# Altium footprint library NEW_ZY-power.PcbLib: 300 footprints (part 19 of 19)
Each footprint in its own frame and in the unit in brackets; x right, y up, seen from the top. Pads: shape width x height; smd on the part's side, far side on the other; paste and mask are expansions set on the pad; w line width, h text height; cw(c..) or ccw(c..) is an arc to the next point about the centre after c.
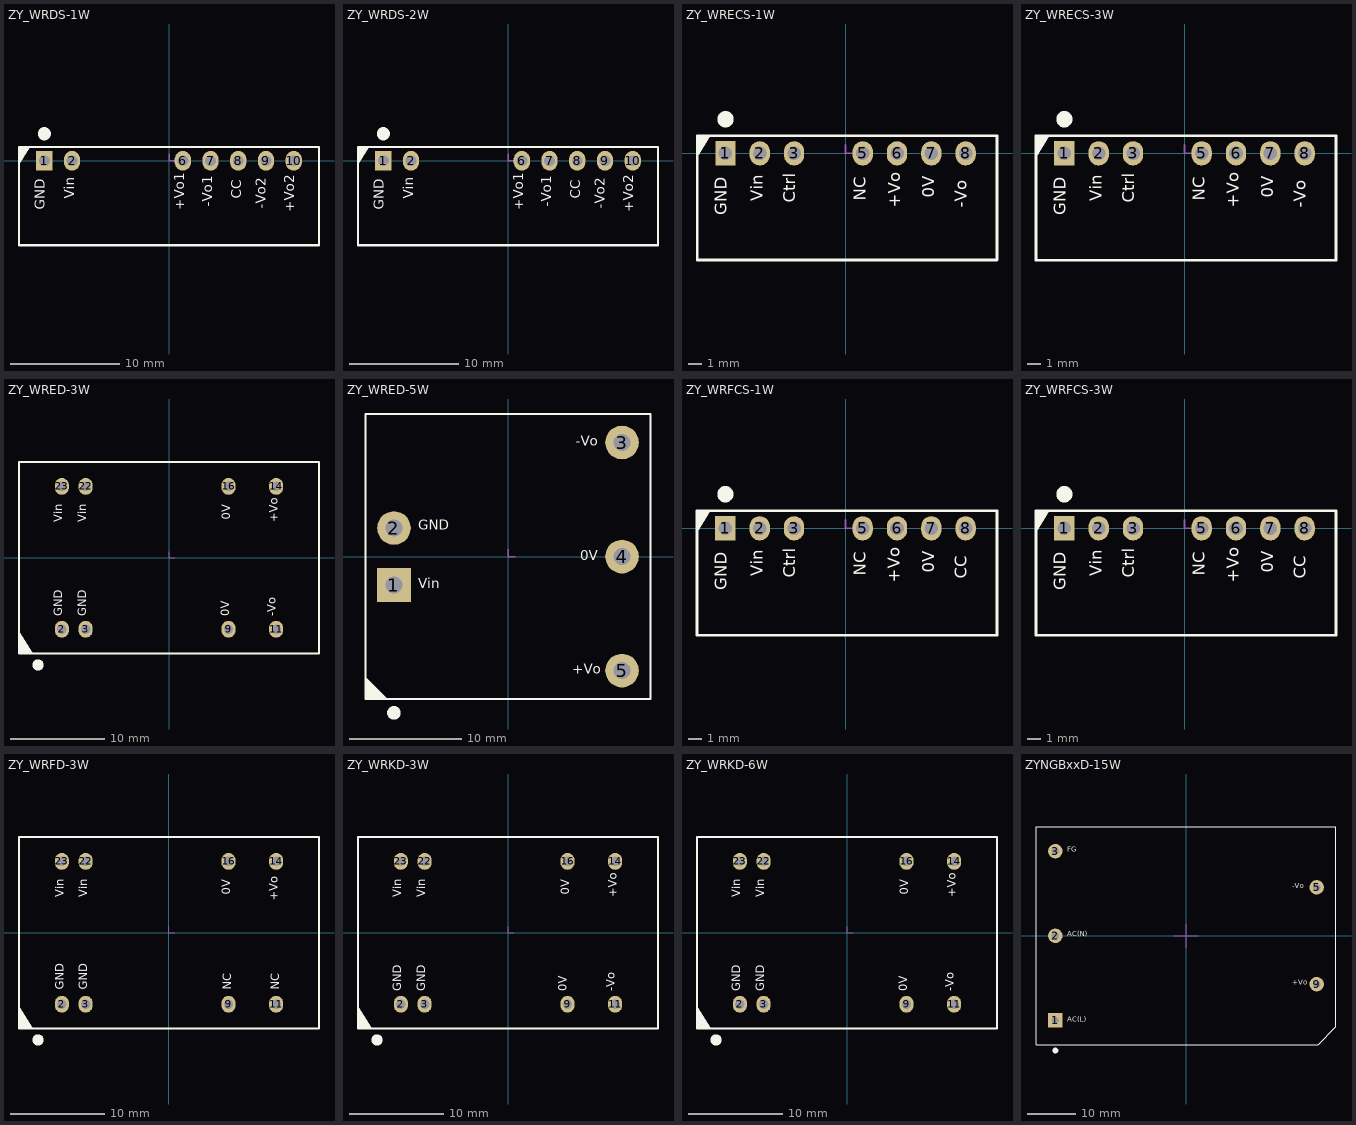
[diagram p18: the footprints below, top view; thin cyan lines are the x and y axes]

## ZY_WRDS-1W [mm]
height 11.5
pads (7):
  rect 1.5x1.8 hole 1: 1(-11.43,0)
  oval 1.5x1.8 hole 1: 2(-8.89,0) 6(1.27,0) 7(3.81,0) 8(6.35,0) 9(8.89,0) 10(11.43,0)
Top Overlay:
  circle w1: c-11.43,2.475 r0.1
  region: -13.75,-0.336 -13.75,1.25 -12.756,1.25
  lines w0.2: -13.75,-7.75 -13.75,1.25 13.75,1.25 13.75,-7.75 -13.75,-7.75
  text "-Vo2" at 9.195,-4.387 h1.52
  text "+Vo2" at 11.811,-4.699 h1.52
  text "CC" at 6.96,-3.469 h1.52
  text "GND" at -11.049,-4.504 h1.52
  text "Vin" at -8.382,-3.494 h1.52
  text "+Vo1" at 1.702,-4.521 h1.52
  text "-Vo1" at 4.267,-4.209 h1.52
Mechanical 15:
  lines w0.127: 0,0.635 0,0 0.635,0

## ZY_WRDS-2W [mm]
height 11.5
pads (7):
  rect 1.5x1.8 hole 1: 1(-11.43,0)
  oval 1.5x1.8 hole 1: 2(-8.89,0) 6(1.27,0) 7(3.81,0) 8(6.35,0) 9(8.89,0) 10(11.43,0)
Top Overlay:
  circle w1: c-11.43,2.475 r0.1
  region: -13.75,-0.336 -13.75,1.25 -12.756,1.25
  lines w0.2: -13.75,-7.75 -13.75,1.25 13.75,1.25 13.75,-7.75 -13.75,-7.75
  text "-Vo2" at 9.195,-4.387 h1.52
  text "+Vo2" at 11.811,-4.699 h1.52
  text "CC" at 6.96,-3.469 h1.52
  text "GND" at -11.049,-4.504 h1.52
  text "Vin" at -8.382,-3.494 h1.52
  text "+Vo1" at 1.702,-4.521 h1.52
  text "-Vo1" at 4.267,-4.209 h1.52
Mechanical 15:
  lines w0.127: 0,0.635 0,0 0.635,0

## ZY_WRECS-1W [mm]
height 12.2
pads (7):
  rect 1.5x1.8 hole 1: 1(-8.89,0)
  oval 1.5x1.8 hole 1: 2(-6.35,0) 3(-3.81,0) 5(1.27,0) 6(3.81,0) 7(6.35,0) 8(8.89,0)
Top Overlay:
  circle w1: c-8.89,2.525 r0.1
  region: -10.998,-0.286 -10.998,1.3 -10.005,1.3
  lines w0.2: -10.99,-7.9 11.21,-7.9 11.21,1.3 -10.99,1.3 -10.99,-7.9
  text "-Vo" at 9.279,-4.03 h1.52
  text "0V" at 6.866,-3.29 h1.52
  text "+Vo" at 4.326,-4.03 h1.52
  text "NC" at 1.786,-3.501 h1.52
  text "Ctrl" at -3.421,-3.646 h1.52
  text "Vin" at -5.834,-3.562 h1.52
  text "GND" at -8.501,-4.572 h1.52
Mechanical 15:
  lines w0.127: 0,0.635 0,0 0.635,0

## ZY_WRECS-3W [mm]
height 12.2
pads (7):
  rect 1.5x1.8 hole 1: 1(-8.89,0)
  oval 1.5x1.8 hole 1: 2(-6.35,0) 3(-3.81,0) 5(1.27,0) 6(3.81,0) 7(6.35,0) 8(8.89,0)
Top Overlay:
  circle w1: c-8.89,2.525 r0.1
  region: -10.99,-0.286 -10.99,1.3 -9.996,1.3
  lines w0.2: -10.99,-7.9 11.21,-7.9 11.21,1.3 -10.99,1.3 -10.99,-7.9
  text "-Vo" at 9.279,-4.03 h1.52
  text "0V" at 6.866,-3.29 h1.52
  text "+Vo" at 4.326,-4.03 h1.52
  text "NC" at 1.786,-3.501 h1.52
  text "Ctrl" at -3.421,-3.646 h1.52
  text "Vin" at -5.834,-3.562 h1.52
  text "GND" at -8.501,-4.572 h1.52
Mechanical 15:
  lines w0.127: 0,0.635 0,0 0.635,0

## ZY_WRED-3W [mm]
height 10.5
pads (8):
  oval 1.5x1.8 hole 1: 2(-11.43,-7.62) 3(-8.89,-7.62) 9(6.35,-7.62) 11(11.43,-7.62) 14(11.43,7.62) 16(6.35,7.62) 22(-8.89,7.62) 23(-11.43,7.62)
Top Overlay:
  circle w1: c-13.97,-11.425 r0.1
  region: -16,-7.87 -16,-10.2 -14.54,-10.2
  lines w0.2: -16,-10.2 -16,10.2 16,10.2 16,-10.2 -16,-10.2
  text "0V" at 6.731,-6.223 h1.52
  text "GND" at -11.049,-6.223 h1.52
  text "GND" at -8.509,-6.223 h1.52
  text "Vin" at -11.049,3.81 h1.52
  text "Vin" at -8.509,3.81 h1.52
  text "-Vo" at 11.684,-6.223 h1.52
  text "+Vo" at 11.938,3.81 h1.52
  text "0V" at 6.858,4.064 h1.52
Mechanical 15:
  lines w0.127: 0,0.635 0,0 0.635,0

## ZY_WRED-5W [mm]
height 11.7
pads (5):
  rect 3x3 hole 1.5: 1(-10.16,-2.54)
  round 3 hole 1.5: 2(-10.16,2.54) 3(10.16,10.16) 4(10.16,0) 5(10.16,-10.16)
Top Overlay:
  circle w1: c-10.16,-13.925 r0.1
  region: -12.7,-12.7 -10.725,-12.7 -12.7,-10.725
  lines w0.2: -12.7,-12.7 12.7,-12.7 12.7,12.7 -12.7,12.7 -12.7,-12.7
  text "0V" at 6.455,-0.635 h1.52
  text "GND" at -8.002,2.057 h1.52
  text "Vin" at -8.001,-3.15 h1.52
  text "+Vo" at 5.715,-10.744 h1.52
  text "-Vo" at 6.027,9.576 h1.52
Mechanical 15:
  lines w0.127: 0,0.635 0,0 0.635,0

## ZY_WRFCS-1W [mm]
height 12.2
pads (7):
  rect 1.5x1.8 hole 1: 1(-8.89,0)
  oval 1.5x1.8 hole 1: 2(-6.35,0) 3(-3.81,0) 5(1.27,0) 6(3.81,0) 7(6.35,0) 8(8.89,0)
Top Overlay:
  circle w1: c-8.89,2.525 r0.1
  region: -10.99,-0.286 -10.99,1.3 -9.996,1.3
  lines w0.2: -10.99,-7.9 11.21,-7.9 11.21,1.3 -10.99,1.3 -10.99,-7.9
  text "CC" at 9.279,-3.718 h1.52
  text "0V" at 6.866,-3.29 h1.52
  text "+Vo" at 4.326,-4.03 h1.52
  text "NC" at 1.786,-3.501 h1.52
  text "Ctrl" at -3.421,-3.646 h1.52
  text "Vin" at -5.834,-3.562 h1.52
  text "GND" at -8.501,-4.572 h1.52
Mechanical 15:
  lines w0.127: 0,0.635 0,0 0.635,0

## ZY_WRFCS-3W [mm]
height 12.2
pads (7):
  rect 1.5x1.8 hole 1: 1(-8.89,0)
  oval 1.5x1.8 hole 1: 2(-6.35,0) 3(-3.81,0) 5(1.27,0) 6(3.81,0) 7(6.35,0) 8(8.89,0)
Top Overlay:
  circle w1: c-8.89,2.525 r0.1
  region: -10.99,-0.286 -10.99,1.3 -9.996,1.3
  lines w0.2: -10.99,-7.9 -10.99,1.3 11.21,1.3 11.21,-7.9 -10.99,-7.9
  text "GND" at -8.501,-4.572 h1.52
  text "Vin" at -5.834,-3.562 h1.52
  text "Ctrl" at -3.421,-3.646 h1.52
  text "NC" at 1.786,-3.501 h1.52
  text "+Vo" at 4.326,-4.03 h1.52
  text "0V" at 6.866,-3.29 h1.52
  text "CC" at 9.279,-3.718 h1.52
Mechanical 15:
  lines w0.127: 0,0.635 0,0 0.635,0

## ZY_WRFD-3W [mm]
height 10.2
pads (8):
  oval 1.5x1.8 hole 1: 2(-11.43,-7.62) 3(-8.89,-7.62) 9(6.35,-7.62) 11(11.43,-7.62) 14(11.43,7.62) 16(6.35,7.62) 22(-8.89,7.62) 23(-11.43,7.62)
Top Overlay:
  circle w1: c-13.97,-11.425 r0.1
  region: -16,-7.87 -16,-10.2 -14.54,-10.2
  lines w0.2: -16,-10.2 -16,10.2 16,10.2 16,-10.2 -16,-10.2
  text "GND" at -10.922,-6.096 h1.52
  text "GND" at -8.382,-6.096 h1.52
  text "Vin" at -10.922,3.81 h1.52
  text "Vin" at -8.382,3.81 h1.52
  text "NC" at 12.065,-6.096 h1.52
  text "+Vo" at 11.938,3.429 h1.52
  text "0V" at 6.858,4.064 h1.52
  text "NC" at 6.985,-6.096 h1.52
Mechanical 15:
  lines w0.127: 0,0.635 0,0 0.635,0

## ZY_WRKD-3W [mm]
height 10.2
pads (8):
  oval 1.5x1.8 hole 1: 2(-11.43,-7.62) 3(-8.89,-7.62) 9(6.35,-7.62) 11(11.43,-7.62) 14(11.43,7.62) 16(6.35,7.62) 22(-8.89,7.62) 23(-11.43,7.62)
Top Overlay:
  circle w1: c-13.97,-11.425 r0.1
  region: -16,-7.87 -16,-10.2 -14.54,-10.2
  lines w0.2: -16,-10.2 -16,10.2 16,10.2 16,-10.2 -16,-10.2
  text "0V" at 6.604,-6.223 h1.52
  text "GND" at -11.049,-6.223 h1.52
  text "GND" at -8.509,-6.223 h1.52
  text "Vin" at -11.049,3.81 h1.52
  text "Vin" at -8.509,3.81 h1.52
  text "-Vo" at 11.684,-6.223 h1.52
  text "+Vo" at 11.938,3.81 h1.52
  text "0V" at 6.858,4.064 h1.52
Mechanical 15:
  lines w0.127: 0,0.635 0,0 0.635,0

## ZY_WRKD-6W [mm]
height 10.5
pads (8):
  oval 1.5x1.8 hole 1: 2(-11.43,-7.62) 3(-8.89,-7.62) 9(6.35,-7.62) 11(11.43,-7.62) 14(11.43,7.62) 16(6.35,7.62) 22(-8.89,7.62) 23(-11.43,7.62)
Top Overlay:
  circle w1: c-13.97,-11.425 r0.1
  region: -16,-7.87 -16,-10.2 -14.54,-10.2
  lines w0.2: -16,-10.2 16,-10.2 16,10.2 -16,10.2 -16,-10.2
  text "0V" at 6.858,4.064 h1.52
  text "+Vo" at 11.938,3.81 h1.52
  text "-Vo" at 11.684,-6.223 h1.52
  text "Vin" at -8.509,3.81 h1.52
  text "Vin" at -11.049,3.81 h1.52
  text "GND" at -8.509,-6.223 h1.52
  text "GND" at -11.049,-6.223 h1.52
  text "0V" at 6.731,-6.223 h1.52
Mechanical 15:
  lines w0.127: 0,0.635 0,0 0.635,0

## ZYNGBxxD-15W [mm] "120426 修改 by kong"
height 22.5
pads (5):
  rect 3x3 hole 1.5: 1(-27,-17.5)
  round 3 hole 1.5: 2(-27,0) 3(-27,17.5) 5(27,10) 9(27,-10)
Top Overlay:
  circle w1: c-27,-23.725 r0.1
  lines w0.2: -31,-22.5 27.325,-22.5 31,-18.825 31,22.5 -31,22.5 -31,-22.5
  text "AC(L)" at -24.587,-18.135 h1.78
  text "AC(N)" at -24.587,-0.482 h1.78
  text "FG" at -24.587,16.917 h1.78
  text "+Vo" at 21.92,-10.515 h1.78
  text "-Vo" at 21.92,9.424 h1.78
Mechanical 15:
  lines w0.152: -2.54,0 2.54,0 ; 0,-2.54 0,2.54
